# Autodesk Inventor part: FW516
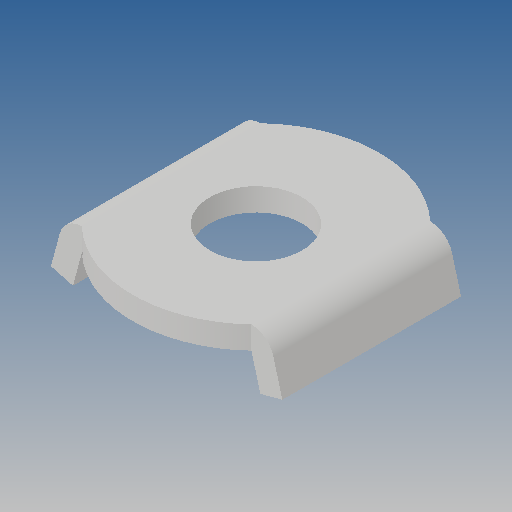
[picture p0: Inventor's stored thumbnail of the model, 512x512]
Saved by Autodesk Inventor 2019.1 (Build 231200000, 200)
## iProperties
Created: 2011-05
Part Number: FW516
Material: Ogólny
Document SubType Name: Modeling
Designer: CADENGINEERING4
Density: 1 g/cm^3
Appearance: Domyślna
Author: CADENGINEERING4
Revision Number: ÈÎºÎ
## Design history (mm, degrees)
feature "ÇÐ³ý-À­Éì4"
node "Bryła1"
